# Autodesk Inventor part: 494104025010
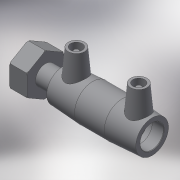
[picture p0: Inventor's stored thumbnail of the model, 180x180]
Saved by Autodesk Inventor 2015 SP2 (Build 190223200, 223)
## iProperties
Created: 2017-06
Part Number: 494104025010
Material: Generic
Description: PLASSON FEMALE FREE NUT TRANSITION COUPLER 25-1"
Document SubType Name: Modeling
Designer: KIM
Mass: 55.0731 g
Surface Area: 148.067 cm^2
Volume: 55.0731 cm^3
Density: 1 g/cm^3
Appearance: Default
Author: KIM
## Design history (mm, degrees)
derived "494104.ipt"
feature "Solid1::494104.ipt"
tag "TaggingFeature1"
body "Solid1"
other parameters: "d0" = 82, "d1" = 25, "d2" = 36, "d4" = 27.33333, "d5" = 32.4, "d6" = 23.75, "d7" = 25, "d8" = 168 deg, "d10" = 16, "d11" = 5.33333, "d29" = 37, "d30" = 14, "d31" = 28.7, "d34" = 5 deg, "d41" = 4, "d42" = 14, "d43" = 0, "d48" = 3, "d49" = 0, "d55" = 33, "d57" = 19, "d80" = 0.5, "d83" = 16.5, "d84" = 10.89, "d85" = 1.089, "d86" = 24.2328, "d87" = 30.291, "d88" = 45.4365, "d89" = 36, "d90" = 0.90873, "d94" = 0, "d95" = 1.089, "d96" = 21.2037, "d_" = 25, "L_" = 115, "D_1" = 36, "A_" = 37, "d_2" = 12, "L_2" = 33, "D_" = 19, "G_" = 30.291
